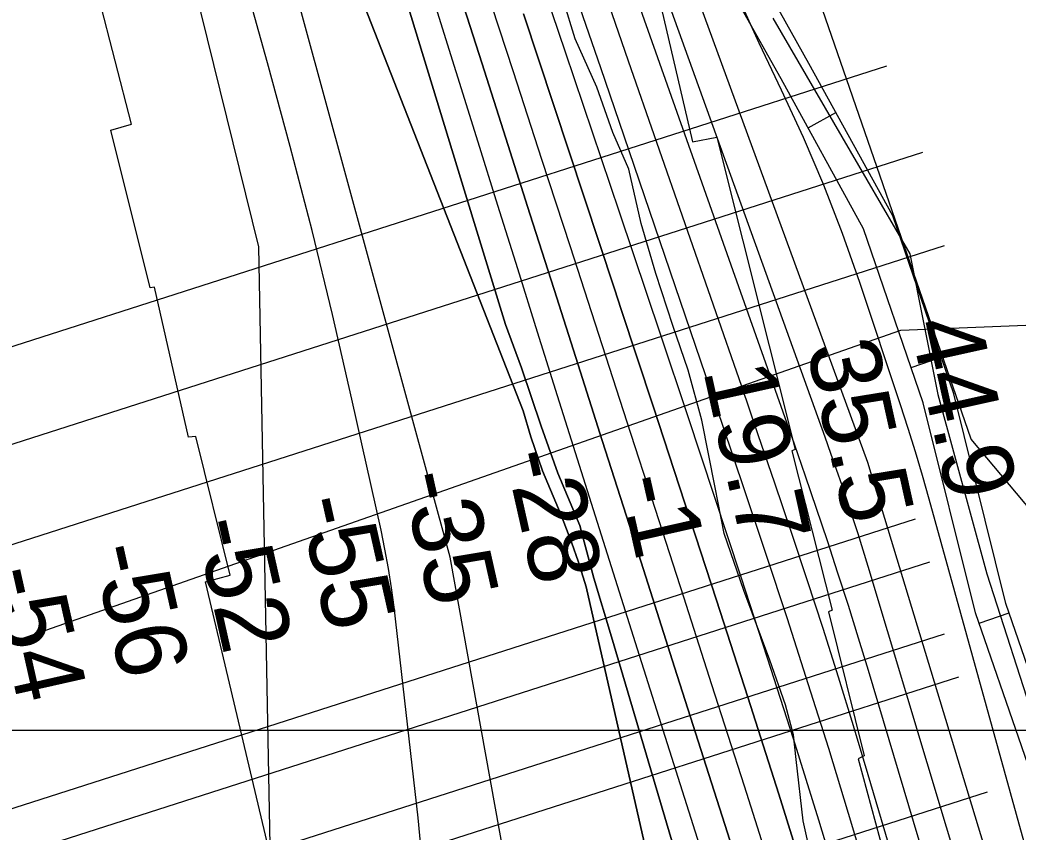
# Model space of a CAD drawing. Extents: x 3250478 to 3288318, y 788638 to 816472.
# Drawn here: x 3275824 to 3276767, y 806041 to 806808 of the extents above; entities that cross this region are included whole.
import ezdxf

# ---------------------------------------------------------------- set-up
doc = ezdxf.new("R2010")
doc.units = 0
for name, color, linetype in [('V-GRID-MAJR', 7, 'Continuous'), ('V-RIVR-EDGE', 7, 'Continuous'), ('V-RIVR-RANG', 7, 'Continuous'), ('V-ROAD-CNTR', 7, 'Continuous'), ('V-RRAP-RVMT', 7, 'Continuous'), ('V-TOPO-DPTH', 7, 'Continuous'), ('V-TOPO-MAJR', 7, 'Continuous'), ('V-TOPO-MINR', 7, 'Continuous'), ('V-TOPO-WATR', 7, 'Continuous'), ('V-UTIL-LINE', 7, 'Continuous')]:
    doc.layers.add(name, color=color, linetype=linetype)

msp = doc.modelspace()

# ---------------------------------------------------------------- linework, layer by layer
at = {"layer": 'V-GRID-MAJR'}
msp.add_spline([(3254645.228, 806146.921), (3259882.848, 806143.493), (3265120.469, 806140.826), (3270358.09, 806138.922), (3275595.711, 806137.779), (3280833.333, 806137.398), (3286070.954, 806137.779), (3286070.955, 806137.779)], degree=3, dxfattribs=at)
at = {"layer": 'V-RIVR-EDGE'}
msp.add_lwpolyline([(3276573.8073258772, 806009.288216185), (3276564.349775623, 806051.9101621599), (3276557.9725801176, 806109.7382627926), (3276555.42256178, 806133.2172442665), (3276547.668248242, 806161.4905655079), (3276532.9935048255, 806203.6907329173), (3276508.3792421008, 806269.3881539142), (3276489.82143035, 806323.3342610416), (3276481.235382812, 806366.8234104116), (3276468.786688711, 806430.3173535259), (3276455.863549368, 806477.7293399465), (3276441.188805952, 806519.9295073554), (3276425.227230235, 806569.0877236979), (3276411.433663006, 806616.0671832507), (3276399.8242267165, 806667.3880339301), (3276384.6965346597, 806702.1997751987), (3276369.588189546, 806744.8356939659), (3276348.8365733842, 806790.5283212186), (3276338.0588710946, 806826.6333437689)], dxfattribs=at)
at = {"layer": 'V-ROAD-CNTR'}
for p, q in [((3276569.0773509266, 806706.4764394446), (3276595.364507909, 806720.9327660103)), ((3276666.5560768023, 806480.051949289), (3276694.9282270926, 806489.7998253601)), ((3276730.6462874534, 806238.5237976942), (3276758.997657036, 806248.3319495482))]:
    msp.add_line(p, q, dxfattribs=at)
for points in [[(3277083.890139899, 805079.4572104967), (3277070.427617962, 805139.6743687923), (3277059.553345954, 805198.3359492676), (3277040.7312496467, 805262.5401107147), (3276996.9284975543, 805459.5112281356), (3276933.083676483, 805719.4833770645), (3276895.4507845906, 805872.5472212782), (3276842.9751199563, 806005.5873302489), (3276755.9660173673, 806257.095184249), (3276706.7598643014, 806455.3626837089), (3276649.069225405, 806623.2769519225), (3276569.8461540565, 806767.3349395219), (3276526.656532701, 806844.7290697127)], [(3277054.4418601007, 805073.6767895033), (3277041.030382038, 805133.6656312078), (3277030.334654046, 805191.3640507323), (3277011.6627503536, 805255.0558892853), (3276967.7155024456, 805452.6767718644), (3276903.950323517, 805712.3246229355), (3276866.8012154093, 805863.4207787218), (3276814.832880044, 805995.1746697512), (3276727.173982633, 806248.5608157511), (3276677.960135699, 806446.859316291), (3276621.5367745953, 806611.0850480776), (3276543.6038459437, 806752.7970604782), (3276499.963467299, 806830.9989302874)], [(3276535.7158913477, 806810.2223522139), (3276624.5537136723, 806657.4216578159), (3276665.261632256, 806587.405797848), (3276691.71957934, 806454.7180632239), (3276738.148486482, 806285.233402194), (3276784.8243931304, 806139.811693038), (3276839.993282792, 805985.6600013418), (3276906.808149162, 805760.5414515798), (3276954.3210541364, 805580.8668109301)]]:
    msp.add_lwpolyline(points, dxfattribs=at)
at = {"layer": 'V-RRAP-RVMT'}
for p, q in [((3275929.775000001, 806710.1659999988), (3275855.727000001, 806997.2829999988)), ((3276426.489000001, 806836.2139999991), (3276459.879000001, 806693.2719999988)), ((3275910.281000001, 806704.207999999), (3275929.775000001, 806710.1659999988)), ((3275947.326000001, 806555.5759999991), (3275910.281000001, 806704.207999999)), ((3276459.879000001, 806693.2719999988), (3276482.738000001, 806697.8559999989)), ((3276482.738000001, 806697.8559999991), (3276556.962000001, 806402.7919999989)), ((3275951.268000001, 806555.8999999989), (3275947.326000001, 806555.5759999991)), ((3275983.486000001, 806414.4639999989), (3275951.268000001, 806555.8999999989)), ((3275990.544000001, 806414.986999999), (3275983.486000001, 806414.4639999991)), ((3276022.998000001, 806283.942999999), (3275990.544000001, 806414.986999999)), ((3276556.962000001, 806402.7919999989), (3276553.7320000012, 806401.6039999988)), ((3276553.7320000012, 806401.6039999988), (3276591.8480000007, 806250.9349999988)), ((3275999.664000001, 806277.599999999), (3276022.998000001, 806283.942999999)), ((3276068.762000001, 805986.2849999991), (3275999.664000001, 806277.599999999)), ((3276591.848000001, 806250.9349999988), (3276588.218000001, 806249.3859999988)), ((3276588.218000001, 806249.385999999), (3276621.968000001, 806113.3619999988)), ((3276621.968000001, 806113.3619999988), (3276616.307000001, 806110.5899999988)), ((3276616.307000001, 806110.589999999), (3276650.838000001, 805984.2989999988))]:
    msp.add_line(p, q, dxfattribs=at)
at = {"layer": 'V-TOPO-DPTH'}
for points in [[(3276810.288810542, 804072.6275164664), (3276651.58, 804741.55), (3276572.443035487, 804909.6768822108), (3276535.141632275, 804994.5768875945), (3276500.8442434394, 805080.5853903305), (3276471.0528761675, 805168.2566390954), (3276444.2655232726, 805257.036385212), (3276382.3170064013, 805483.4448482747), (3276376.5172848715, 805505.8927179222), (3276371.1469223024, 805528.4364307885), (3276366.4205981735, 805551.1239084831), (3276362.1236330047, 805573.9072293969), (3276230.8767673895, 806300.9788998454), (3276054.0628592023, 806947.9319073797)], [(3276810.288810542, 804072.6275164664), (3276651.58, 804741.55), (3276572.443035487, 804909.6768822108), (3276535.141632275, 804994.5768875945), (3276500.8442434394, 805080.5853903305), (3276471.0528761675, 805168.2566390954), (3276444.2655232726, 805257.036385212), (3276382.3170064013, 805483.4448482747), (3276376.5172848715, 805505.8927179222), (3276371.1469223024, 805528.4364307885), (3276366.4205981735, 805551.1239084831), (3276362.1236330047, 805573.9072293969), (3276230.8767673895, 806300.9788998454), (3276054.0628592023, 806947.9319073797)], [(3276672.918147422, 804913.3931827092), (3276526.757238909, 805546.2056824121), (3276525.549926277, 805551.3087786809), (3276524.3065078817, 805556.4028579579), (3276523.0089308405, 805561.4834117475), (3276521.6752480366, 805566.5549485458), (3276521.0406722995, 805568.9168344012), (3276519.325348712, 805575.1517336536), (3276517.560353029, 805581.3722164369), (3276515.7208492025, 805587.5710745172), (3276513.831673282, 805593.755516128), (3276359.381703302, 806272.9404399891), (3276351.8901369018, 806297.3490147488), (3276345.6740957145, 806314.2316632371), (3276335.739711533, 806340.7371900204), (3276318.078584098, 806382.7042740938), (3276307.0004027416, 806414.6833874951), (3276299.7775568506, 806439.1733269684), (3276109.1485293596, 806925.5136038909)], [(3276109.1485293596, 806925.5136038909), (3276299.7775568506, 806439.1733269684), (3276307.0004027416, 806414.6833874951), (3276318.078584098, 806382.7042740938), (3276335.739711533, 806340.7371900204), (3276345.6740957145, 806314.2316632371), (3276351.8901369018, 806297.3490147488), (3276359.381703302, 806272.9404399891), (3276513.831673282, 805593.755516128), (3276515.7208492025, 805587.5710745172), (3276517.560353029, 805581.3722164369), (3276519.325348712, 805575.1517336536), (3276521.0406722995, 805568.9168344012), (3276521.6752480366, 805566.5549485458), (3276523.0089308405, 805561.4834117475), (3276524.3065078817, 805556.4028579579), (3276525.549926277, 805551.3087786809), (3276526.757238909, 805546.2056824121), (3276672.918147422, 804913.3931827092)], [(3276693.055725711, 805083.2632630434), (3276591.8311997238, 805504.1969175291), (3276584.2085568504, 805535.2260435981), (3276576.383978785, 805566.2031094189), (3276568.25649793, 805597.1020848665), (3276559.9270818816, 805627.9490000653), (3276556.275905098, 805641.2123252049), (3276545.7616085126, 805678.5904638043), (3276534.970315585, 805715.8867788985), (3276523.7635281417, 805753.0603587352), (3276512.2797443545, 805790.1521150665), (3276383.2039915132, 806225.8799072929), (3276366.646684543, 806281.099754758), (3276353.4008389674, 806330.7976174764), (3276332.428250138, 806380.4954801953), (3276316.974763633, 806424.6713581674), (3276298.209815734, 806479.8912056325), (3276283.15332589, 806520.6780383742), (3276268.3397689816, 806568.9471288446), (3276253.5421309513, 806617.2211090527), (3276165.8530307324, 806903.5399033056)], [(3276165.8530307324, 806903.5399033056), (3276253.5421309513, 806617.2211090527), (3276268.3397689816, 806568.9471288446), (3276283.15332589, 806520.6780383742), (3276298.209815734, 806479.8912056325), (3276316.974763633, 806424.6713581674), (3276332.428250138, 806380.4954801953), (3276353.4008389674, 806330.7976174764), (3276366.646684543, 806281.099754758), (3276383.2039915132, 806225.8799072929), (3276512.2797443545, 805790.1521150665), (3276523.7635281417, 805753.0603587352), (3276534.970315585, 805715.8867788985), (3276545.7616085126, 805678.5904638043), (3276556.275905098, 805641.2123252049), (3276559.9270818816, 805627.9490000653), (3276568.25649793, 805597.1020848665), (3276576.383978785, 805566.2031094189), (3276584.2085568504, 805535.2260435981), (3276591.8311997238, 805504.1969175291), (3276693.055725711, 805083.2632630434)], [(3276224.26823082, 806882.0436330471), (3276260.6591469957, 806768.0728230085), (3276283.445309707, 806696.6987629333), (3276306.2271192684, 806625.3233136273), (3276329.0023991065, 806553.9457804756), (3276351.7733257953, 806482.5668580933), (3276374.548515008, 806411.1892976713), (3276397.3337407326, 806339.8149424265), (3276420.134021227, 806268.4453949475), (3276442.9443382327, 806197.0790526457), (3276510.254667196, 805986.5626651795), (3276531.593719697, 805918.5940551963), (3276552.4546225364, 805850.4817461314), (3276572.5983008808, 805782.153888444), (3276592.263829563, 805713.6823316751), (3276598.6702799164, 805690.9261165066), (3276614.5172652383, 805633.6567294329), (3276630.0221615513, 805576.2965111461), (3276645.0139243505, 805518.8000460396), (3276659.6635981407, 805461.2127497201), (3276712.0781476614, 805251.2515883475), (3276732.157657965, 805170.9774862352), (3276752.2872812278, 805090.7159774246)], [(3276752.2872812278, 805090.7159774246), (3276732.157657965, 805170.9774862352), (3276712.0781476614, 805251.2515883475), (3276659.6635981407, 805461.2127497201), (3276645.0139243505, 805518.8000460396), (3276630.0221615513, 805576.2965111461), (3276614.5172652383, 805633.6567294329), (3276598.6702799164, 805690.9261165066), (3276592.263829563, 805713.6823316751), (3276572.5983008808, 805782.153888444), (3276552.4546225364, 805850.4817461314), (3276531.593719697, 805918.5940551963), (3276510.254667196, 805986.5626651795), (3276442.9443382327, 806197.0790526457), (3276420.134021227, 806268.4453949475), (3276397.3337407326, 806339.8149424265), (3276374.548515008, 806411.1892976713), (3276351.7733257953, 806482.5668580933), (3276329.0023991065, 806553.9457804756), (3276306.2271192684, 806625.3233136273), (3276283.445309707, 806696.6987629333), (3276260.6591469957, 806768.0728230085), (3276224.26823082, 806882.0436330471)], [(3276937.706767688, 804777.4657163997), (3276722.2215922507, 805667.0917967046), (3276702.11102135, 805736.6687970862), (3276625.779183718, 805997.2303041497), (3276607.414006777, 806058.7961323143), (3276588.6463935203, 806120.2368647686), (3276569.2751257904, 806181.4899536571), (3276549.5014217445, 806242.6179468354), (3276529.320529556, 806303.6167901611), (3276508.999250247, 806364.5685587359), (3276488.467390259, 806425.4497151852), (3276467.795143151, 806486.2837968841), (3276395.237685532, 806698.5998092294), (3276373.084867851, 806763.2836244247), (3276350.875271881, 806827.9478967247)], [(3276300.027626, 806814.2766432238), (3276328.760794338, 806727.6911777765), (3276357.4329378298, 806641.0854852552), (3276386.0643980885, 806554.466308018), (3276392.4726029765, 806535.0565231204), (3276422.5926016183, 806443.5752119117), (3276452.612890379, 806352.0612820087), (3276482.483614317, 806260.4984240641), (3276512.2546283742, 806168.9029474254), (3276541.486773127, 806077.141151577), (3276570.10028138, 805985.1902601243), (3276597.785834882, 805892.9557252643), (3276624.852751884, 805800.5320948), (3276637.8422635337, 805755.3346317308), (3276661.6946568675, 805671.059868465), (3276685.0924718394, 805586.6610558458), (3276707.8084192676, 805502.0761691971), (3276730.069788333, 805417.3672331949), (3276735.627613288, 805395.8660312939), (3276760.303067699, 805300.3073015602), (3276784.9467328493, 805204.7403828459), (3276809.5427141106, 805109.16118066)], [(3276300.027626, 806814.2766432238), (3276328.760794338, 806727.6911777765), (3276357.4329378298, 806641.0854852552), (3276386.0643980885, 806554.466308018), (3276392.4726029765, 806535.0565231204), (3276422.5926016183, 806443.5752119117), (3276452.612890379, 806352.0612820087), (3276482.483614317, 806260.4984240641), (3276512.2546283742, 806168.9029474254), (3276541.486773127, 806077.141151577), (3276570.10028138, 805985.1902601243), (3276597.785834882, 805892.9557252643), (3276624.852751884, 805800.5320948), (3276637.8422635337, 805755.3346317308), (3276661.6946568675, 805671.059868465), (3276685.0924718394, 805586.6610558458), (3276707.8084192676, 805502.0761691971), (3276730.069788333, 805417.3672331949), (3276735.627613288, 805395.8660312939), (3276760.303067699, 805300.3073015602), (3276784.9467328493, 805204.7403828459), (3276809.5427141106, 805109.16118066)]]:
    msp.add_lwpolyline(points, dxfattribs=at)
at = {"layer": 'V-TOPO-MAJR'}
for points in [[(3276204.52220099, 806014.8275032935), (3276200.71098665, 806054.9166850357), (3276177.7741305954, 806253.8518066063), (3276175.374010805, 806272.1518834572), (3276172.5952419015, 806290.388199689), (3276169.2484993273, 806308.5288749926), (3276165.523107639, 806326.6057896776), (3276137.9934008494, 806450.3789144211), (3276119.573472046, 806530.1325480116), (3276100.293994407, 806609.6704267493), (3276079.7251935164, 806688.884673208), (3276058.29684379, 806767.883164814), (3276001.428538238, 806970.9919510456)], [(3277026.3382514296, 804881.710675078), (3276883.0246543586, 805420.6637003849), (3276874.372840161, 805452.9568692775), (3276865.640590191, 805485.2281115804), (3276856.7876865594, 805517.4664639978), (3276847.8543471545, 805549.6828898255), (3276838.7655297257, 805581.8552784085), (3276829.5498569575, 805613.9908809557), (3276820.14390118, 805646.07130445), (3276810.6110900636, 805678.1149419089), (3276625.939350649, 806292.2075043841), (3276621.232713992, 806307.5822801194), (3276616.425007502, 806322.9248347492), (3276611.465696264, 806338.2190577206), (3276606.4053151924, 806353.4810595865), (3276601.2225187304, 806368.70265153), (3276595.977599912, 806383.9025938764), (3276590.639497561, 806399.0700618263), (3276585.239272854, 806414.2158801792), (3276407.057194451, 806909.1504838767)]]:
    msp.add_lwpolyline(points, dxfattribs=at)
at = {"layer": 'V-TOPO-MINR'}
for points in [[(3277213.965033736, 804061.5239987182), (3277189.7097817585, 804226.2525191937), (3277161.8519663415, 804383.7811491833), (3277110.5889789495, 804642.5108046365), (3277106.2597036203, 804670.2676004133), (3277101.5015813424, 804697.9455208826), (3277096.1001886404, 804725.5051283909), (3277090.269948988, 804752.9858605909), (3277083.95032502, 804780.3662073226), (3277077.407651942, 804807.6917002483), (3277070.530405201, 804834.9349124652), (3277063.430109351, 804862.1232708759), (3276892.406808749, 805500.9556565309), (3276887.053381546, 805520.7799842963), (3276881.6425750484, 805540.5885044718), (3276876.145699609, 805560.3733132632), (3276870.591444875, 805580.142314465), (3276864.940070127, 805599.8836014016), (3276859.2165888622, 805619.6037457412), (3276853.38494782, 805639.2921761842), (3276847.4812002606, 805658.9594640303), (3276625.69, 806390.52), (3276410.4744326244, 806977.9101885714)], [(3276810.288810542, 804072.6275164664), (3276651.58, 804741.55), (3276572.443035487, 804909.6768822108), (3276535.141632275, 804994.5768875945), (3276500.8442434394, 805080.5853903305), (3276471.0528761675, 805168.2566390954), (3276444.2655232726, 805257.036385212), (3276382.3170064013, 805483.4448482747), (3276376.5172848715, 805505.8927179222), (3276371.1469223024, 805528.4364307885), (3276366.4205981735, 805551.1239084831), (3276362.1236330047, 805573.9072293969), (3276230.8767673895, 806300.9788998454), (3276054.0628592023, 806947.9319073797)], [(3276672.918147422, 804913.3931827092), (3276526.757238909, 805546.2056824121), (3276525.549926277, 805551.3087786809), (3276524.3065078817, 805556.4028579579), (3276523.0089308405, 805561.4834117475), (3276521.6752480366, 805566.5549485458), (3276521.0406722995, 805568.9168344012), (3276519.325348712, 805575.1517336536), (3276517.560353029, 805581.3722164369), (3276515.7208492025, 805587.5710745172), (3276513.831673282, 805593.755516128), (3276359.381703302, 806272.9404399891), (3276351.8901369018, 806297.3490147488), (3276345.6740957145, 806314.2316632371), (3276335.739711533, 806340.7371900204), (3276318.078584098, 806382.7042740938), (3276307.0004027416, 806414.6833874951), (3276299.7775568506, 806439.1733269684), (3276109.1485293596, 806925.5136038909)], [(3276693.055725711, 805083.2632630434), (3276591.8311997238, 805504.1969175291), (3276584.2085568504, 805535.2260435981), (3276576.383978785, 805566.2031094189), (3276568.25649793, 805597.1020848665), (3276559.9270818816, 805627.9490000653), (3276556.275905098, 805641.2123252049), (3276545.7616085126, 805678.5904638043), (3276534.970315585, 805715.8867788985), (3276523.7635281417, 805753.0603587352), (3276512.2797443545, 805790.1521150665), (3276383.2039915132, 806225.8799072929), (3276366.646684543, 806281.099754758), (3276353.4008389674, 806330.7976174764), (3276332.428250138, 806380.4954801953), (3276316.974763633, 806424.6713581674), (3276298.209815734, 806479.8912056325), (3276283.15332589, 806520.6780383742), (3276268.3397689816, 806568.9471288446), (3276253.5421309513, 806617.2211090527), (3276165.8530307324, 806903.5399033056)], [(3276719.212003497, 805100.3745623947), (3276702.701629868, 805167.4920181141), (3276625.414180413, 805482.8197931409), (3276614.3527830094, 805527.05320697), (3276603.016163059, 805571.214594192), (3276591.2667092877, 805615.2679415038), (3276579.2420329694, 805659.2492622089), (3276574.18017777, 805677.428570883), (3276559.1329149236, 805730.3605367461), (3276543.7054881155, 805783.1792289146), (3276527.7078153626, 805835.828010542), (3276511.3299786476, 805888.3635184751), (3276407.8589021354, 806214.0612175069), (3276388.8877326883, 806273.896019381), (3276369.962347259, 806333.7452700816), (3276351.105637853, 806393.6161940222), (3276332.294712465, 806453.5015667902), (3276313.52423709, 806513.399689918), (3276294.761910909, 806573.300364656), (3276276.011808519, 806633.204866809), (3276257.2698553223, 806693.1119205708), (3276194.8416799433, 806892.7297262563)], [(3276752.2872812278, 805090.7159774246), (3276732.157657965, 805170.9774862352), (3276712.0781476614, 805251.2515883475), (3276659.6635981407, 805461.2127497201), (3276645.0139243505, 805518.8000460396), (3276630.0221615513, 805576.2965111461), (3276614.5172652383, 805633.6567294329), (3276598.6702799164, 805690.9261165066), (3276592.263829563, 805713.6823316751), (3276572.5983008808, 805782.153888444), (3276552.4546225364, 805850.4817461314), (3276531.593719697, 805918.5940551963), (3276510.254667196, 805986.5626651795), (3276442.9443382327, 806197.0790526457), (3276420.134021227, 806268.4453949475), (3276397.3337407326, 806339.8149424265), (3276374.548515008, 806411.1892976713), (3276351.7733257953, 806482.5668580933), (3276329.0023991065, 806553.9457804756), (3276306.2271192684, 806625.3233136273), (3276283.445309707, 806696.6987629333), (3276260.6591469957, 806768.0728230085), (3276224.26823082, 806882.0436330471)], [(3276627.9800810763, 804087.3481327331), (3276503.9385327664, 804675.0357746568), (3276499.4017512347, 804695.3619888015), (3276494.5531646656, 804715.6097076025), (3276489.2368705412, 804735.7396833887), (3276483.60877138, 804755.7911638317), (3276424.989915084, 804955.7043142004), (3276408.7130838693, 805005.3455916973), (3276390.4075238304, 805054.1520083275), (3276175.3517610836, 805423.2611393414), (3276165.079761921, 805454.9751039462), (3276155.491336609, 805486.8826230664), (3276146.9282720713, 805519.080473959), (3276139.0487813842, 805551.4718793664), (3276122.9571023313, 805622.5555600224), (3276107.699651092, 805690.6679576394), (3276092.647501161, 805758.8252089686), (3276077.9033031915, 805827.0497408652), (3276063.3644065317, 805895.3191264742), (3276049.983599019, 806594.1404375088), (3275983.379435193, 806864.7991635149)], [(3276914.1124340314, 804773.1829270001), (3276666.7029249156, 805756.5732061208), (3276625.4022389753, 805898.8858458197), (3276602.644414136, 805975.8738297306), (3276579.378721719, 806052.7052668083), (3276555.351227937, 806129.301883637), (3276530.8158665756, 806205.7419536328), (3276505.802227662, 806282.0323666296), (3276480.658870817, 806358.2798201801), (3276455.320937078, 806434.4628345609), (3276429.8532854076, 806510.602889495), (3276390.7811112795, 806626.922285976), (3276365.350329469, 806702.5047501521), (3276339.8688775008, 806778.0700994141), (3276314.3114202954, 806853.6097763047)], [(3276792.4287293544, 805054.5336691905), (3276768.666723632, 805147.8718004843), (3276744.9239215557, 805241.2148185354), (3276721.193921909, 805334.5610944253), (3276694.5559991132, 805439.3913757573), (3276676.1718474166, 805510.4728877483), (3276657.3859621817, 805581.4462360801), (3276637.997476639, 805652.2573389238), (3276618.207257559, 805722.9602781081), (3276610.5193616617, 805749.9832075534), (3276586.15386648, 805833.9861520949), (3276561.2152078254, 805917.8153749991), (3276535.416803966, 806001.3840154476), (3276509.0452366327, 806084.7789342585), (3276478.2671149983, 806180.3975958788), (3276451.593036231, 806263.1647661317), (3276424.879529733, 806345.9191933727), (3276398.106881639, 806428.6545060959), (3276371.294805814, 806511.3770758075), (3276344.436782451, 806594.0847618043), (3276317.55692349, 806676.7853458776), (3276290.644311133, 806759.4752770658), (3276263.709863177, 806842.1581063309)], [(3277012.0675157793, 804812.6428602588), (3277002.746556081, 804849.639792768), (3276989.420320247, 804901.1175710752), (3276873.5120307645, 805340.0136168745), (3276861.599612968, 805384.8359430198), (3276849.5935151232, 805429.6330042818), (3276837.446897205, 805474.3921682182), (3276825.2065992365, 805519.1260672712), (3276812.754625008, 805563.8004708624), (3276800.1141155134, 805608.420817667), (3276787.19080312, 805652.9600792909), (3276774.078955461, 805697.4452841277), (3276626.040866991, 806193.8892646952), (3276616.703468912, 806224.6494190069), (3276607.165295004, 806255.3461042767), (3276597.325957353, 806285.9475859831), (3276587.2858438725, 806316.4855986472), (3276577.015360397, 806346.9485651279), (3276566.6385444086, 806377.3749555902), (3276556.1022296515, 806407.7464820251), (3276545.4595823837, 806438.0814324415), (3276403.376943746, 806839.6865992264)], [(3276784.6690255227, 805990.7311672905), (3276683.5132090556, 806355.8300936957), (3276677.1345508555, 806378.1949341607), (3276670.5320149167, 806400.4916374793), (3276663.593662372, 806422.6861350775), (3276656.431432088, 806444.812495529), (3276618.0422593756, 806560.4228062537), (3276601.644330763, 806606.7107438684), (3276584.0437516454, 806652.5088787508), (3276564.6391967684, 806697.5723095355), (3276544.031991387, 806742.145937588), (3276522.990821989, 806786.560199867), (3276502.577439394, 806831.2532829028)], [(3276937.706767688, 804777.4657163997), (3276722.2215922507, 805667.0917967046), (3276702.11102135, 805736.6687970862), (3276625.779183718, 805997.2303041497), (3276607.414006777, 806058.7961323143), (3276588.6463935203, 806120.2368647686), (3276569.2751257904, 806181.4899536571), (3276549.5014217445, 806242.6179468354), (3276529.320529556, 806303.6167901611), (3276508.999250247, 806364.5685587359), (3276488.467390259, 806425.4497151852), (3276467.795143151, 806486.2837968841), (3276395.237685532, 806698.5998092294), (3276373.084867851, 806763.2836244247), (3276350.875271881, 806827.9478967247)], [(3276984.3381521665, 804796.0740227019), (3276969.0391193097, 804856.8682015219), (3276952.679922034, 804920.3463132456), (3276863.866058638, 805258.9792458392), (3276848.7307489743, 805316.3952054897), (3276833.4998311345, 805373.7856636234), (3276818.1255010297, 805431.137869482), (3276802.655562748, 805488.4645738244), (3276786.920238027, 805545.7172695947), (3276770.9267017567, 805602.8967969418), (3276754.5458481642, 805659.9665716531), (3276737.906783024, 805716.9631779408), (3276625.9898234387, 806095.555312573), (3276612.098545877, 806141.7135225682), (3276597.90680221, 806187.7775484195), (3276583.2643593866, 806233.7002980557), (3276568.3214504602, 806279.5288635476), (3276553.053629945, 806325.2529834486), (3276537.6531327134, 806370.932049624), (3276522.053620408, 806416.5435352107), (3276506.3214313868, 806462.109967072), (3276399.4366809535, 806769.5150204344), (3276380.6393386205, 806823.4354220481)], [(3277202.0500000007, 805683.74), (3277082.906669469, 805966.3217032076), (3277074.128056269, 805984.2434584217), (3277064.11261441, 806001.3441800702), (3277052.241929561, 806017.2133513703), (3277039.1344160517, 806032.261489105), (3277039.06100556, 806032.3367349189), (3277025.0296177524, 806046.7078613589), (3277010.9908697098, 806061.071788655), (3276996.9410813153, 806075.4249172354), (3276982.8839326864, 806089.7708466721), (3276969.773489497, 806104.7467057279), (3276957.8961210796, 806120.5452775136), (3276947.868364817, 806137.5779183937), (3276939.0736833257, 806155.4332720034), (3276723.2800000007, 806412.3200000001), (3276582.568623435, 806818.4114401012)]]:
    msp.add_lwpolyline(points, dxfattribs=at)
at = {"layer": 'V-TOPO-WATR'}
msp.add_lwpolyline([(3276809.5427141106, 805109.16118066), (3276784.9467328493, 805204.7403828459), (3276760.303067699, 805300.3073015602), (3276735.627613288, 805395.8660312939), (3276730.069788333, 805417.3672331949), (3276707.8084192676, 805502.0761691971), (3276685.0924718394, 805586.6610558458), (3276661.6946568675, 805671.059868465), (3276637.8422635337, 805755.3346317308), (3276624.852751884, 805800.5320948), (3276597.785834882, 805892.9557252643), (3276570.10028138, 805985.1902601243), (3276541.486773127, 806077.141151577), (3276512.2546283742, 806168.9029474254), (3276482.483614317, 806260.4984240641), (3276452.612890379, 806352.0612820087), (3276422.5926016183, 806443.5752119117), (3276392.4726029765, 806535.0565231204), (3276386.0643980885, 806554.466308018), (3276357.4329378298, 806641.0854852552), (3276328.760794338, 806727.6911777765), (3276300.027626, 806814.2766432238)], dxfattribs=at)
at = {"layer": 'V-UTIL-LINE'}
for p, q in [((3274186.18, 805977.5750000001), (3276643.558, 806765.022)), ((3274220.1210000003, 805896.115), (3276677.5, 806683.563)), ((3274240.486, 805807.867), (3276697.865, 806595.3150000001)), ((3274213.332, 805549.909), (3276670.711, 806337.357)), ((3274226.91, 805509.179), (3276684.289, 806296.626)), ((3274240.484, 805441.296), (3276697.863, 806228.743)), ((3274254.063, 805400.5650000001), (3276711.441, 806188.013)), ((3274281.215, 805291.953), (3276738.594, 806079.4010000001))]:
    msp.add_line(p, q, dxfattribs=at)
msp.add_lwpolyline([(3275141.896, 805984.118), (3276656.77, 806515.544), (3276877.286, 806524.156), (3277840.19, 806866.721), (3278355.395, 807030.15), (3278608.833, 807099.192), (3280710.704, 807649.4890000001), (3281180.975, 807775.1190000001), (3281615.44, 807894.738)], dxfattribs=at)

# ---------------------------------------------------------------- texts
at = {"layer": 'V-RIVR-RANG'}
for s, rotation, p in [('44.9', 282.4583257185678, (3276664.9046586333, 806521.2573929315)), ('35.5', 282.4583257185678, (3276567.367563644, 806499.1938245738)), ('19.7', 282.4583257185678, (3276469.774563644, 806477.3868245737)), ('-28', 282.69097222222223, (3276282.2018640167, 806397.7675410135)), ('-35', 282.69097222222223, (3276184.2601617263, 806377.5045520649)), ('-1', 282.69097222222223, (3276390.0520815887, 806374.0252149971)), ('-55', 282.69097222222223, (3276087.014864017, 806354.1545410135)), ('-52', 282.69097222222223, (3275989.1890624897, 806333.3778817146)), ('-56', 282.69097222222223, (3275892.1755663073, 806308.9975299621)), ('-54', 282.69097222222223, (3275794.6405166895, 806286.9341947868))]:
    msp.add_text(s, height=67, rotation=rotation, dxfattribs=at).set_placement(p)

doc.saveas('drawing.dxf')
